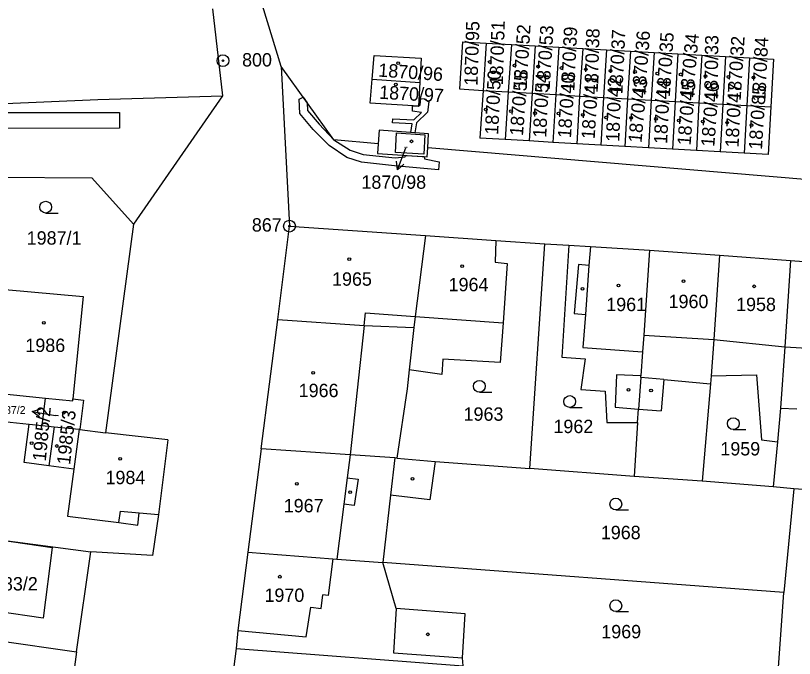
# Model space of a CAD drawing. Extents: x -755819 to -753140, y -1169796 to -1166000.
# Drawn here: x -755357.1 to -755258.2, y -1167922.4 to -1167840.7 of the extents above; entities that cross this region are included whole.
import ezdxf

# ---------------------------------------------------------------- set-up
doc = ezdxf.new("R2010")
doc.units = 0
for name, color, linetype in [('Vrstva 1', 7, 'Continuous'), ('Vrstva 16', 7, 'Continuous'), ('Vrstva 17', 7, 'Continuous'), ('Vrstva 18', 7, 'Continuous'), ('Vrstva 19', 7, 'Continuous'), ('Vrstva 24', 7, 'Continuous'), ('Vrstva 25', 7, 'Continuous'), ('Vrstva 27', 7, 'Continuous'), ('Vrstva 4', 7, 'Continuous'), ('Vrstva 62', 7, 'Continuous')]:
    doc.layers.add(name, color=color, linetype=linetype)

msp = doc.modelspace()

# ---------------------------------------------------------------- linework, layer by layer
at = {"layer": 'Vrstva 1'}
for p, q in [((-755323.4, -1167847.14), (-755325.75, -1167839.4)), ((-755332.12, -1167839.81), (-755330.85, -1167850.86)), ((-755300.35, -1167844), (-755300.74, -1167850)), ((-755300.35, -1167844), (-755297.35, -1167844.17)), ((-755297.35, -1167844.17), (-755297.74, -1167850.2)), ((-755297.35, -1167844.17), (-755294.15, -1167844.35)), ((-755294.15, -1167844.35), (-755294.55, -1167850.38)), ((-755294.15, -1167844.35), (-755291.13, -1167844.52)), ((-755291.13, -1167844.52), (-755291.52, -1167850.55)), ((-755291.13, -1167844.52), (-755288.1, -1167844.68)), ((-755288.1, -1167844.68), (-755288.5, -1167850.72)), ((-755288.1, -1167844.68), (-755285.08, -1167844.85)), ((-755285.08, -1167844.85), (-755285.47, -1167850.9)), ((-755285.08, -1167844.85), (-755282.05, -1167845.02)), ((-755282.05, -1167845.02), (-755282.45, -1167851.07)), ((-755282.05, -1167845.02), (-755279.03, -1167845.19)), ((-755279.03, -1167845.19), (-755279.41, -1167851.24)), ((-755279.03, -1167845.19), (-755276, -1167845.36)), ((-755276, -1167845.36), (-755276.38, -1167851.41)), ((-755276, -1167845.36), (-755272.98, -1167845.52)), ((-755311.83, -1167848.75), (-755311.58, -1167845.74)), ((-755311.58, -1167845.74), (-755305.61, -1167846.1)), ((-755305.61, -1167846.1), (-755305.77, -1167849.17)), ((-755272.98, -1167845.52), (-755273.34, -1167851.58)), ((-755272.98, -1167845.52), (-755269.95, -1167845.69)), ((-755269.95, -1167845.69), (-755270.31, -1167851.75)), ((-755269.95, -1167845.69), (-755266.92, -1167845.86)), ((-755266.92, -1167845.86), (-755267.27, -1167851.93)), ((-755266.92, -1167845.86), (-755263.87, -1167846.03)), ((-755263.87, -1167846.03), (-755264.23, -1167852.1)), ((-755263.87, -1167846.03), (-755260.85, -1167846.2)), ((-755260.85, -1167846.2), (-755261.19, -1167852.27)), ((-755316.69, -1167856.49), (-755323.4, -1167847.14)), ((-755323.4, -1167847.14), (-755322.34, -1167867.44)), ((-755312.07, -1167851.8), (-755311.83, -1167848.75)), ((-755311.83, -1167848.75), (-755305.77, -1167849.17)), ((-755305.77, -1167849.17), (-755305.93, -1167852.21)), ((-755300.74, -1167850), (-755297.74, -1167850.2)), ((-755297.74, -1167850.2), (-755298.14, -1167856.26)), ((-755297.74, -1167850.2), (-755294.55, -1167850.38)), ((-755346.71, -1167851.33), (-755330.85, -1167850.86)), ((-755330.85, -1167850.86), (-755342.14, -1167867.17)), ((-755294.55, -1167850.38), (-755294.94, -1167856.44)), ((-755294.55, -1167850.38), (-755291.52, -1167850.55)), ((-755291.52, -1167850.55), (-755291.9, -1167856.61)), ((-755291.52, -1167850.55), (-755288.5, -1167850.72)), ((-755288.5, -1167850.72), (-755288.87, -1167856.79)), ((-755288.5, -1167850.72), (-755285.47, -1167850.9)), ((-755285.47, -1167850.9), (-755285.83, -1167856.96)), ((-755285.47, -1167850.9), (-755282.45, -1167851.07)), ((-755282.45, -1167851.07), (-755282.79, -1167857.13)), ((-755282.45, -1167851.07), (-755279.41, -1167851.24)), ((-755279.41, -1167851.24), (-755279.75, -1167857.31)), ((-755279.41, -1167851.24), (-755276.38, -1167851.41)), ((-755361.16, -1167851.95), (-755346.71, -1167851.33)), ((-755305.93, -1167852.21), (-755312.07, -1167851.8)), ((-755276.38, -1167851.41), (-755276.71, -1167857.48)), ((-755276.38, -1167851.41), (-755273.34, -1167851.58)), ((-755273.34, -1167851.58), (-755273.68, -1167857.65)), ((-755273.34, -1167851.58), (-755270.31, -1167851.75)), ((-755270.31, -1167851.75), (-755270.64, -1167857.82)), ((-755270.31, -1167851.75), (-755267.27, -1167851.93)), ((-755267.27, -1167851.93), (-755267.6, -1167858)), ((-755267.27, -1167851.93), (-755264.23, -1167852.1)), ((-755264.23, -1167852.1), (-755264.56, -1167858.17)), ((-755264.23, -1167852.1), (-755261.19, -1167852.27)), ((-755261.19, -1167852.27), (-755261.51, -1167858.34)), ((-755310.94, -1167855.26), (-755311.07, -1167856.96)), ((-755304.68, -1167855.7), (-755310.94, -1167855.26)), ((-755304.78, -1167857.49), (-755304.68, -1167855.7)), ((-755294.94, -1167856.44), (-755298.14, -1167856.26)), ((-755311.07, -1167856.96), (-755316.69, -1167856.49)), ((-755311.07, -1167856.96), (-755311.16, -1167858.2)), ((-755291.9, -1167856.61), (-755294.94, -1167856.44)), ((-755288.87, -1167856.79), (-755291.9, -1167856.61)), ((-755285.83, -1167856.96), (-755288.87, -1167856.79)), ((-755282.79, -1167857.13), (-755285.83, -1167856.96)), ((-755279.75, -1167857.31), (-755282.79, -1167857.13)), ((-755311.16, -1167858.2), (-755304.85, -1167858.62)), ((-755304.85, -1167858.62), (-755304.78, -1167857.49)), ((-755202.51, -1167866.05), (-755304.78, -1167857.49)), ((-755276.71, -1167857.48), (-755279.75, -1167857.31)), ((-755273.68, -1167857.65), (-755276.71, -1167857.48)), ((-755270.64, -1167857.82), (-755273.68, -1167857.65)), ((-755267.6, -1167858), (-755270.64, -1167857.82)), ((-755264.56, -1167858.17), (-755267.6, -1167858)), ((-755261.51, -1167858.34), (-755264.56, -1167858.17)), ((-755362.4, -1167861.2), (-755347.44, -1167861.29)), ((-755347.44, -1167861.29), (-755342.14, -1167867.17)), ((-755342.14, -1167867.17), (-755345.7, -1167893.71)), ((-755323.81, -1167879.3), (-755322.34, -1167867.44)), ((-755322.34, -1167867.44), (-755305.07, -1167868.64)), ((-755305.07, -1167868.64), (-755306.38, -1167878.91)), ((-755305.07, -1167868.64), (-755296.12, -1167869.26)), ((-755296.12, -1167869.26), (-755296.22, -1167872.01)), ((-755296.12, -1167869.26), (-755289.9, -1167869.7)), ((-755291.78, -1167898.24), (-755289.9, -1167869.7)), ((-755289.9, -1167869.7), (-755286.84, -1167869.87)), ((-755286.84, -1167869.87), (-755287.72, -1167884.07)), ((-755286.84, -1167869.87), (-755284.1, -1167870.03)), ((-755284.1, -1167870.03), (-755276.59, -1167870.47)), ((-755276.59, -1167870.47), (-755277.33, -1167881.3)), ((-755276.59, -1167870.47), (-755267.7, -1167871.14)), ((-755296.22, -1167872.01), (-755294.68, -1167872.17)), ((-755267.7, -1167871.14), (-755268.44, -1167881.83)), ((-755267.7, -1167871.14), (-755258.66, -1167871.81)), ((-755258.66, -1167871.81), (-755259.41, -1167882.78)), ((-755258.66, -1167871.81), (-755249.59, -1167872.54)), ((-755294.68, -1167872.17), (-755295.19, -1167879.73)), ((-755358.45, -1167875.48), (-755348.57, -1167876.39)), ((-755348.57, -1167876.39), (-755349.86, -1167889.4)), ((-755306.38, -1167878.91), (-755306.53, -1167880.32)), ((-755325.92, -1167895.75), (-755323.81, -1167879.3)), ((-755323.81, -1167879.3), (-755312.85, -1167880.05)), ((-755295.19, -1167879.73), (-755295.57, -1167884.76)), ((-755312.85, -1167880.05), (-755306.53, -1167880.32)), ((-755306.53, -1167880.32), (-755307.13, -1167885.72)), ((-755277.33, -1167881.3), (-755277.48, -1167883.42)), ((-755268.44, -1167881.83), (-755268.76, -1167886.47)), ((-755259.41, -1167882.78), (-755259.94, -1167890.56)), ((-755277.48, -1167883.42), (-755277.69, -1167886.48)), ((-755302.85, -1167884.34), (-755302.97, -1167886.29)), ((-755295.57, -1167884.76), (-755302.85, -1167884.34)), ((-755287.72, -1167884.07), (-755284.75, -1167884.28)), ((-755284.75, -1167884.28), (-755285.32, -1167888.2)), ((-755307.13, -1167885.72), (-755307.4, -1167888.13)), ((-755302.97, -1167886.29), (-755307.13, -1167885.72)), ((-755277.7, -1167886.67), (-755277.99, -1167890.69)), ((-755277.7, -1167886.67), (-755277.69, -1167886.48)), ((-755268.76, -1167886.47), (-755268.85, -1167887.46)), ((-755268.76, -1167886.47), (-755263, -1167886.33)), ((-755263, -1167886.33), (-755262.38, -1167894.59)), ((-755268.85, -1167887.46), (-755269.9, -1167899.84)), ((-755307.4, -1167888.13), (-755308.69, -1167896.91)), ((-755285.32, -1167888.2), (-755282.23, -1167888.42)), ((-755282.23, -1167888.42), (-755282.01, -1167892.4)), ((-755353.77, -1167892.77), (-755353.35, -1167889.29)), ((-755353.35, -1167889.29), (-755349.89, -1167889.65)), ((-755349.89, -1167889.65), (-755349.86, -1167889.4)), ((-755349.86, -1167889.4), (-755348.51, -1167889.54)), ((-755348.51, -1167889.54), (-755348.99, -1167893.27)), ((-755278.1, -1167892.41), (-755277.99, -1167890.69)), ((-755259.94, -1167890.56), (-755260.34, -1167894.86)), ((-755259.94, -1167890.56), (-755257.87, -1167890.65)), ((-755360.15, -1167892.1), (-755355.42, -1167892.59)), ((-755356.06, -1167897.48), (-755355.42, -1167892.59)), ((-755355.42, -1167892.59), (-755353.77, -1167892.77)), ((-755353.77, -1167892.77), (-755352.25, -1167892.93)), ((-755282.01, -1167892.4), (-755278.1, -1167892.41)), ((-755278.1, -1167892.41), (-755278.55, -1167899.25)), ((-755352.25, -1167892.93), (-755352.91, -1167897.9)), ((-755352.25, -1167892.93), (-755349.08, -1167893.26)), ((-755349.08, -1167893.26), (-755349.75, -1167898.32)), ((-755348.99, -1167893.27), (-755349.08, -1167893.26)), ((-755348.99, -1167893.27), (-755345.7, -1167893.71)), ((-755337.81, -1167894.58), (-755345.7, -1167893.71)), ((-755337.81, -1167894.58), (-755338.99, -1167904.1)), ((-755262.38, -1167894.59), (-755260.34, -1167894.86)), ((-755260.34, -1167894.86), (-755260.87, -1167900.58)), ((-755325.92, -1167895.75), (-755327.65, -1167908.89)), ((-755314.63, -1167896.5), (-755325.92, -1167895.75)), ((-755308.94, -1167896.89), (-755314.63, -1167896.5)), ((-755352.91, -1167897.9), (-755356.06, -1167897.48)), ((-755308.69, -1167896.91), (-755308.94, -1167896.89)), ((-755308.69, -1167896.91), (-755303.85, -1167897.34)), ((-755303.85, -1167897.34), (-755304.49, -1167902.21)), ((-755303.85, -1167897.34), (-755291.78, -1167898.24)), ((-755349.75, -1167898.32), (-755352.91, -1167897.9)), ((-755349.75, -1167898.32), (-755350.54, -1167904.31)), ((-755278.55, -1167899.25), (-755291.78, -1167898.24)), ((-755269.9, -1167899.84), (-755278.55, -1167899.25)), ((-755260.87, -1167900.58), (-755269.9, -1167899.84)), ((-755258.26, -1167900.82), (-755260.87, -1167900.58)), ((-755309.51, -1167901.63), (-755310.48, -1167910.2)), ((-755304.49, -1167902.21), (-755309.51, -1167901.63)), ((-755258.26, -1167900.82), (-755259.52, -1167914.01)), ((-755252.12, -1167901.31), (-755258.26, -1167900.82)), ((-755350.54, -1167904.31), (-755344.01, -1167905.12)), ((-755341.6, -1167905.42), (-755341.42, -1167903.89)), ((-755341.42, -1167903.89), (-755338.99, -1167904.1)), ((-755338.99, -1167904.1), (-755339.73, -1167909.29)), ((-755344.01, -1167905.12), (-755341.6, -1167905.42)), ((-755361.42, -1167906.99), (-755347.57, -1167908.83)), ((-755349.41, -1167921.53), (-755347.57, -1167908.83)), ((-755339.73, -1167909.29), (-755347.57, -1167908.83)), ((-755327.65, -1167908.89), (-755328.92, -1167918.84)), ((-755327.65, -1167908.89), (-755316.83, -1167909.72)), ((-755316.83, -1167909.72), (-755316.34, -1167909.76)), ((-755316.34, -1167909.76), (-755310.48, -1167910.2)), ((-755308.8, -1167916.03), (-755310.48, -1167910.2)), ((-755259.52, -1167914.01), (-755310.48, -1167910.2)), ((-755260.4, -1167926.37), (-755259.52, -1167914.01)), ((-755300.02, -1167916.7), (-755308.8, -1167916.03)), ((-755300.35, -1167922.3), (-755300.02, -1167916.7)), ((-755366.28, -1167919.16), (-755349.41, -1167921.53)), ((-755328.92, -1167918.84), (-755329.12, -1167921.13)), ((-755349.41, -1167921.53), (-755351.12, -1167934.03)), ((-755329.12, -1167921.13), (-755331.58, -1167940.3)), ((-755329.12, -1167921.13), (-755300.27, -1167923.33)), ((-755300.27, -1167923.33), (-755300.35, -1167922.3))]:
    msp.add_line(p, q, dxfattribs=at)
at = {"layer": 'Vrstva 16'}
for p, q in [((-755308.627, -1167860.296), (-755307.54, -1167857.5)), ((-755307.53, -1167857.45), (-755307.54, -1167857.5)), ((-755355.017, -1167890.993), (-755352.06, -1167891.5)), ((-755351.75, -1167891.56), (-755352.06, -1167891.5))]:
    msp.add_line(p, q, dxfattribs=at)
for points in [[(-755307.798, -1167859.545), (-755308.627, -1167860.296), (-755308.73, -1167859.183)], [(-755354.116, -1167891.655), (-755355.017, -1167890.993), (-755353.947, -1167890.669)]]:
    msp.add_lwpolyline(points, dxfattribs=at)
at = {"layer": 'Vrstva 24'}
for centre, radius in [((-755330.8, -1167846.41), 0.75), ((-755330.8, -1167846.41), 0.1), ((-755322.34, -1167867.44), 0.75), ((-755322.34, -1167867.44), 0.1)]:
    msp.add_circle(centre, radius, dxfattribs=at)
at = {"layer": 'Vrstva 25'}
for p, q in [((-755353.32, -1167865.77), (-755351.72, -1167865.77)), ((-755298.21, -1167888.54), (-755296.61, -1167888.54)), ((-755286.73, -1167890.48), (-755285.13, -1167890.48)), ((-755265.95, -1167893.28), (-755264.35, -1167893.28)), ((-755280.88, -1167903.51), (-755279.28, -1167903.51)), ((-755280.88, -1167916.43), (-755279.28, -1167916.43))]:
    msp.add_line(p, q, dxfattribs=at)
for centre, radius in [((-755308.54, -1167846.73), 0.175), ((-755296.9, -1167846.58), 0.175), ((-755293.76, -1167847.02), 0.175), ((-755290.75, -1167847.14), 0.175), ((-755287.78, -1167847.34), 0.175), ((-755284.68, -1167847.51), 0.175), ((-755281.54, -1167847.71), 0.175), ((-755278.44, -1167847.83), 0.175), ((-755275.6, -1167848.03), 0.175), ((-755272.63, -1167848.15), 0.175), ((-755269.49, -1167848.39), 0.175), ((-755266.56, -1167848.48), 0.175), ((-755308.84, -1167849.43), 0.175), ((-755263.38, -1167848.56), 0.175), ((-755297.38, -1167852.63), 0.175), ((-755294.19, -1167852.83), 0.175), ((-755291.14, -1167853.08), 0.175), ((-755288.17, -1167853.12), 0.175), ((-755285.07, -1167853.28), 0.175), ((-755282.1, -1167853.64), 0.175), ((-755278.92, -1167853.68), 0.175), ((-755275.77, -1167853.8), 0.175), ((-755272.85, -1167854), 0.175), ((-755269.83, -1167854.13), 0.175), ((-755266.74, -1167854.29), 0.175), ((-755263.64, -1167854.61), 0.175), ((-755306.84, -1167856.66), 0.175), ((-755353.32, -1167865.02), 0.75), ((-755314.74, -1167871.65), 0.175), ((-755300.39, -1167872.51), 0.175), ((-755280.53, -1167874.98), 0.175), ((-755272.27, -1167874.44), 0.175), ((-755263.31, -1167875.09), 0.175), ((-755285.12, -1167875.41), 0.175), ((-755353.57, -1167879.74), 0.175), ((-755319.33, -1167886.07), 0.175), ((-755298.21, -1167887.79), 0.75), ((-755279.27, -1167888.23), 0.175), ((-755276.4, -1167888.33), 0.175), ((-755286.73, -1167889.73), 0.75), ((-755351.01, -1167891.14), 0.175), ((-755265.95, -1167892.53), 0.75), ((-755355.1, -1167895.02), 0.175), ((-755351.91, -1167895.38), 0.175), ((-755343.85, -1167897.02), 0.175), ((-755306.71, -1167899.54), 0.175), ((-755321.4, -1167900.18), 0.175), ((-755314.63, -1167901.25), 0.175), ((-755280.88, -1167902.76), 0.75), ((-755323.58, -1167911.99), 0.175), ((-755280.88, -1167915.68), 0.75), ((-755304.75, -1167919.31), 0.175)]:
    msp.add_circle(centre, radius, dxfattribs=at)
at = {"layer": 'Vrstva 27'}
for p, q in [((-755321.09, -1167851.3), (-755320.61, -1167851.03)), ((-755321.02, -1167853.11), (-755321.09, -1167851.3)), ((-755320.61, -1167851.03), (-755320.08, -1167851.77)), ((-755305.73, -1167852.03), (-755305.67, -1167851.23)), ((-755305.67, -1167851.23), (-755305.17, -1167851.27)), ((-755305.17, -1167851.27), (-755304.64, -1167851.62)), ((-755320.08, -1167851.77), (-755320.04, -1167852.73)), ((-755306.71, -1167852.81), (-755306.7, -1167852.16)), ((-755306.7, -1167852.16), (-755305.93, -1167852.21)), ((-755305.93, -1167852.21), (-755305.73, -1167852.03)), ((-755304.64, -1167851.62), (-755304.8, -1167852.96)), ((-755369.67, -1167853.02), (-755343.92, -1167852.99)), ((-755343.92, -1167852.99), (-755343.92, -1167854.99)), ((-755319.33, -1167855.17), (-755321.02, -1167853.11)), ((-755320.04, -1167852.73), (-755318.59, -1167854.49)), ((-755305.57, -1167853), (-755306.71, -1167852.81)), ((-755306.54, -1167853.93), (-755305.57, -1167853)), ((-755304.8, -1167852.96), (-755306.22, -1167854.31)), ((-755309.24, -1167854.3), (-755309.21, -1167853.8)), ((-755309.21, -1167853.8), (-755306.54, -1167853.93)), ((-755343.92, -1167854.99), (-755369.63, -1167855.02)), ((-755317.29, -1167857.21), (-755319.33, -1167855.17)), ((-755318.59, -1167854.49), (-755316.69, -1167856.49)), ((-755306.74, -1167854.43), (-755309.24, -1167854.3)), ((-755306.92, -1167855.54), (-755306.74, -1167854.43)), ((-755306.22, -1167854.31), (-755306.41, -1167855.58)), ((-755306.41, -1167855.58), (-755306.92, -1167855.54)), ((-755315.06, -1167858.7), (-755317.29, -1167857.21)), ((-755316.69, -1167856.49), (-755314.62, -1167857.8)), ((-755314.62, -1167857.8), (-755312.98, -1167858.33)), ((-755313.18, -1167859.31), (-755315.06, -1167858.7)), ((-755312.98, -1167858.33), (-755308.91, -1167858.76)), ((-755308.91, -1167858.76), (-755307.66, -1167858.64)), ((-755307.66, -1167858.64), (-755307.61, -1167858.44)), ((-755307.61, -1167858.44), (-755305.24, -1167858.59)), ((-755305.24, -1167858.59), (-755305.19, -1167858.88)), ((-755305.19, -1167858.88), (-755303.3, -1167859.28)), ((-755309.01, -1167859.76), (-755313.18, -1167859.31)), ((-755303.39, -1167860.28), (-755309.01, -1167859.76)), ((-755303.3, -1167859.28), (-755303.39, -1167860.28))]:
    msp.add_line(p, q, dxfattribs=at)
at = {"layer": 'Vrstva 4'}
for p, q in [((-755308.89, -1167858.07), (-755308.76, -1167855.56)), ((-755308.76, -1167855.56), (-755305.14, -1167855.82)), ((-755305.14, -1167855.82), (-755305.29, -1167858.29)), ((-755305.29, -1167858.29), (-755308.89, -1167858.07)), ((-755284.1, -1167870.03), (-755284.29, -1167872.42)), ((-755285.61, -1167872.3), (-755286.16, -1167878.54)), ((-755284.29, -1167872.42), (-755285.61, -1167872.3)), ((-755284.29, -1167872.42), (-755284.73, -1167878.68)), ((-755312.85, -1167880.05), (-755312.67, -1167878.45)), ((-755312.67, -1167878.45), (-755306.38, -1167878.91)), ((-755306.38, -1167878.91), (-755295.19, -1167879.73)), ((-755286.16, -1167878.54), (-755284.73, -1167878.68)), ((-755284.73, -1167878.68), (-755285.06, -1167882.87)), ((-755312.85, -1167880.05), (-755314.63, -1167896.5)), ((-755277.33, -1167881.3), (-755268.44, -1167881.83)), ((-755268.44, -1167881.83), (-755259.41, -1167882.78)), ((-755285.06, -1167882.87), (-755277.48, -1167883.42)), ((-755259.41, -1167882.78), (-755250.32, -1167883.28)), ((-755280.79, -1167886.33), (-755280.94, -1167890.46)), ((-755277.69, -1167886.48), (-755280.79, -1167886.33)), ((-755274.78, -1167886.91), (-755277.7, -1167886.67)), ((-755274.78, -1167886.91), (-755275.11, -1167890.92)), ((-755274.78, -1167886.91), (-755268.85, -1167887.46)), ((-755359.85, -1167888.62), (-755353.35, -1167889.29)), ((-755280.94, -1167890.46), (-755277.99, -1167890.69)), ((-755277.99, -1167890.69), (-755275.11, -1167890.92)), ((-755314.63, -1167896.5), (-755315, -1167899.41)), ((-755308.94, -1167896.89), (-755309.51, -1167901.63)), ((-755315, -1167899.41), (-755315.44, -1167902.77)), ((-755315, -1167899.41), (-755313.61, -1167899.59)), ((-755313.61, -1167899.59), (-755314.14, -1167902.94)), ((-755315.44, -1167902.77), (-755316.34, -1167909.76)), ((-755314.14, -1167902.94), (-755315.44, -1167902.77)), ((-755344.01, -1167905.12), (-755343.83, -1167903.68)), ((-755343.83, -1167903.68), (-755341.42, -1167903.89)), ((-755361.42, -1167906.99), (-755352.49, -1167908.28)), ((-755352.49, -1167908.28), (-755353.65, -1167917.25)), ((-755316.83, -1167909.72), (-755317.43, -1167914.38)), ((-755318.33, -1167916.03), (-755318.12, -1167914.3)), ((-755317.43, -1167914.38), (-755318.12, -1167914.3)), ((-755353.65, -1167917.25), (-755364.46, -1167915.72)), ((-755320.24, -1167919.61), (-755319.62, -1167915.84)), ((-755319.62, -1167915.84), (-755318.33, -1167916.03)), ((-755308.8, -1167916.03), (-755309.14, -1167921.68)), ((-755328.92, -1167918.84), (-755320.24, -1167919.61)), ((-755309.14, -1167921.68), (-755300.35, -1167922.3))]:
    msp.add_line(p, q, dxfattribs=at)

# ---------------------------------------------------------------- texts
at = {"layer": 'Vrstva 16'}
msp.add_text('1870/98', height=1.7, dxfattribs=at).set_placement((-755313.198, -1167862.69))
at = {"layer": 'Vrstva 17'}
for s, p in [('800', (-755328.363, -1167847.15)), ('867', (-755327.123, -1167868.13))]:
    msp.add_text(s, height=1.7, dxfattribs=at).set_placement(p)
at = {"layer": 'Vrstva 18'}
msp.add_text('1870/95', height=1.7, rotation=88.17821, dxfattribs=at).set_placement((-755298.451, -1167849.613))
for s, p in [('1987/1', (-755355.727, -1167869.79)), ('1963', (-755300.217, -1167892.17)), ('1962', (-755288.797, -1167893.74)), ('1959', (-755267.587, -1167896.58)), ('1968', (-755282.777, -1167907.22)), ('1969', (-755282.717, -1167919.82))]:
    msp.add_text(s, height=1.7, dxfattribs=at).set_placement(p)
at = {"layer": 'Vrstva 19'}
for s, rotation, p in [('1870/51', 88.17821, (-755295.231, -1167849.563)), ('1870/52', 86.40204, (-755292.213, -1167850.053)), ('1870/53', 86.40204, (-755289.283, -1167850.173)), ('1870/39', 87.31877, (-755286.147, -1167850.333)), ('1870/38', 88.17821, (-755283.181, -1167850.533)), ('1870/37', 87.31877, (-755280.037, -1167850.693)), ('1870/36', 85.4853, (-755277.148, -1167850.854)), ('1870/35', 86.40204, (-755274.013, -1167851.053)), ('1870/34', 84.62587, (-755271.074, -1167851.224)), ('1870/33', 89.09494, (-755267.956, -1167851.383)), ('1870/32', 86.40204, (-755265.013, -1167851.543)), ('1870/84', 87.31877, (-755261.877, -1167851.663)), ('1870/96', 355.97868, (-755311.097, -1167848.428)), ('1870/50', 87.31877, (-755295.827, -1167855.853)), ('1870/55', 85.4853, (-755292.678, -1167856.014)), ('1870/54', 87.31877, (-755289.717, -1167856.223)), ('1870/40', 86.40204, (-755286.573, -1167856.303)), ('1870/41', 86.40204, (-755283.563, -1167856.423)), ('1870/42', 88.17821, (-755280.431, -1167856.743)), ('1870/43', 84.62587, (-755277.614, -1167856.904)), ('1870/44', 87.31877, (-755274.357, -1167857.023)), ('1870/45', 85.4853, (-755271.378, -1167857.224)), ('1870/46', 85.4853, (-755268.368, -1167857.394)), ('1870/47', 87.31877, (-755265.277, -1167857.473)), ('1870/97', 356.78082, (-755310.977, -1167851.245)), ('1870/85', 86.40204, (-755262.303, -1167857.753)), ('1985/2', 84.56857, (-755353.305, -1167897.368)), ('1985/3', 83.88102, (-755350.222, -1167897.818))]:
    msp.add_text(s, height=1.7, rotation=rotation, dxfattribs=at).set_placement(p)
for s, height, p in [('1870/98', 0.1, (-755307.795, -1167857.45)), ('1965', 1.7, (-755316.927, -1167875.01)), ('1964', 1.7, (-755302.117, -1167875.71)), ('1961', 1.7, (-755282.087, -1167878.24)), ('1960', 1.7, (-755274.167, -1167877.86)), ('1958', 1.7, (-755265.587, -1167878.23)), ('1986', 1.7, (-755355.897, -1167883.43)), ('1966', 1.7, (-755321.167, -1167889.17)), ('1987/2', 0.1, (-755351.976, -1167891.56)), ('1984', 1.7, (-755345.717, -1167900.23)), ('1967', 1.7, (-755323.067, -1167903.81)), ('1983/2', 1.7, (-755361.277, -1167913.74)), ('1970', 1.7, (-755325.517, -1167915.19))]:
    msp.add_text(s, height=height, dxfattribs=at).set_placement(p)
at = {"layer": 'Vrstva 62'}
msp.add_text('1987/2', height=1, dxfattribs=at).set_placement((-755359.968, -1167891.31))

doc.saveas('drawing.dxf')
